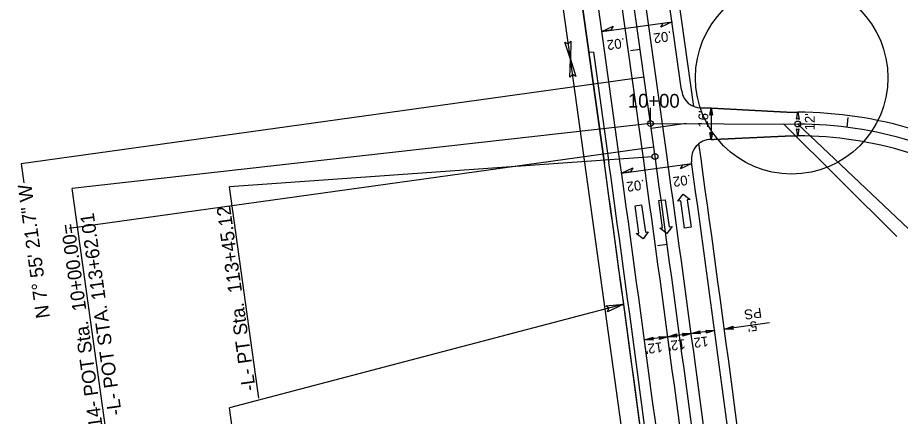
# Model space of a CAD drawing. Extents: x 472216 to 481979, y 489069 to 507339.
# Drawn here: x 477703.5 to 478152.3, y 497819.2 to 498021.9 of the extents above; entities that cross this region are included whole.
import ezdxf

# ---------------------------------------------------------------- set-up
doc = ezdxf.new("R2010")
doc.units = 0
for name, color, linetype in [('Old_Level_12', 7, 'Continuous'), ('Prop Drainage Structure Drop Inlet Grate 2 Narrow Slots and Sag Grates 840 24 CELL', 7, 'Continuous'), ('Prop Drainage Structure Drop Inlet Grate 2 Wide Slots and Sag Grates 840 22 Label', 7, 'Continuous'), ('Prop Drainage Structure Outlet Berm Ditch 850 10 CELL', 7, 'Continuous'), ('Prop Drainage Structure Pipe CSP 15in', 7, 'Continuous'), ('Prop Drainage Structure Pipe RCP 15in Class III Label', 7, 'Continuous'), ('Prop Drainage Structure Pipe RCP 24in Class III Label', 7, 'Continuous'), ('Prop Drainage Structure Pipe Side Drain 15in Label', 7, 'Continuous'), ('Prop Drainage Structure Tops and Inverts LABEL', 7, 'Continuous'), ('Prop Earthen Structure False Sump CELL', 7, 'Continuous'), ('Prop Erosion Embankment Toe Protection CELL', 7, 'Continuous'), ('Sheet Block Revision CELL', 7, 'Continuous'), ('Sheet Block Title CELL', 7, 'Continuous'), ('Sheet Clip Boundary CELL', 7, 'Continuous'), ('Sheet North Arrow Point CELL', 7, 'Continuous'), ('Sheet PE Seal Cell', 7, 'Continuous'), ('Sheet Plan And Profile CELL', 7, 'Continuous'), ('Sheet Plot Border Outside CELL', 7, 'Continuous'), ('Sheet Profile Grid Major CELL', 7, 'Continuous'), ('Sheet Profile Grid Minor CELL', 7, 'Continuous')]:
    doc.layers.add(name, color=color, linetype=linetype)

msp = doc.modelspace()

# ---------------------------------------------------------------- linework, layer by layer
at = {"layer": 'Old_Level_12'}
for p, q in [((478021.95, 497991.61), (477705.24, 497947.53)), ((478025.23, 497968.03), (477731.27, 497934.92)), ((478150.49, 497910.65), (478092.82, 497967.81)), ((478100.1, 497967.78), (478162.88, 497908.21)), ((478026.07, 497951.1), (477811.27, 497935.77)), ((477705.24, 497947.53), (477706.59, 497937.85)), ((477751.11, 497792.38), (477731.27, 497934.92)), ((477826.2, 497828.47), (477811.27, 497935.77))]:
    msp.add_line(p, q, dxfattribs=at)
for centre in [(478025.23, 497968.03), (478025.23, 497968.03), (478100.1, 497967.78), (478027.55, 497951.3), (478027.55, 497951.3)]:
    msp.add_circle(centre, 1.5, dxfattribs=at)
at = {"layer": 'Prop Drainage Structure Drop Inlet Grate 2 Narrow Slots and Sag Grates 840 24 CELL'}
for points in [[(478000.54, 498014.81), (478006.21, 498017.61), (478005.12, 498015.44)], [(478036.2, 498019.77), (478030.53, 498016.96), (478031.62, 498019.13)], [(478010.57, 497942.78), (478016.23, 497945.58), (478015.15, 497943.41)], [(478046.22, 497947.74), (478040.56, 497944.93), (478041.64, 497947.1)]]:
    msp.add_lwpolyline(points, close=True, dxfattribs=at)
at = {"layer": 'Prop Drainage Structure Drop Inlet Grate 2 Wide Slots and Sag Grates 840 22 Label'}
for p, q in [((478000.54, 498014.81), (478036.2, 498019.77)), ((478010.57, 497942.78), (478046.22, 497947.74))]:
    msp.add_line(p, q, dxfattribs=at)
at = {"layer": 'Prop Drainage Structure Outlet Berm Ditch 850 10 CELL'}
for points in [[(477984.81, 498009.85), (477984.51, 498000.72), (477981.68, 498009.46), (477983.42, 498008.55)], [(477984.22, 497991.59), (477984.51, 498000.72), (477987.34, 497991.98), (477985.6, 497992.9)], [(478055.47, 497972.33), (478056.1, 497975.93), (478056.73, 497972.31), (478056.09, 497972.77)], [(478099.49, 497970.19), (478100.12, 497973.78), (478100.75, 497970.16), (478100.11, 497970.62)], [(478056.68, 497963.53), (478056.05, 497959.93), (478055.42, 497963.55), (478056.06, 497963.09)], [(478100.71, 497965.38), (478100.08, 497961.78), (478099.45, 497965.41), (478100.09, 497964.94)], [(478002.54, 497875.38), (478011.64, 497876.17), (478003.3, 497872.32), (478004, 497874.16)], [(478067.42, 497863.38), (478062.86, 497863.54), (478067.23, 497864.94), (478066.77, 497864.07)], [(478038.68, 497859.48), (478034.12, 497859.65), (478038.5, 497861.05), (478038.04, 497860.18)], [(478041.45, 497861.42), (478046.01, 497861.26), (478041.64, 497859.86), (478042.1, 497860.73)], [(478050.58, 497861.09), (478046.01, 497861.26), (478050.39, 497862.66), (478049.93, 497861.79)], [(478053.34, 497863.03), (478057.9, 497862.87), (478053.53, 497861.47), (478053.99, 497862.34)], [(478026.79, 497857.87), (478022.23, 497858.04), (478026.61, 497859.44), (478026.14, 497858.57)], [(478029.56, 497859.81), (478034.12, 497859.65), (478029.74, 497858.25), (478030.21, 497859.12)]]:
    msp.add_lwpolyline(points, close=True, dxfattribs=at)
at = {"layer": 'Prop Drainage Structure Pipe RCP 15in Class III Label'}
for p, q in [((478033.5, 497952.13), (477983.76, 498309.54)), ((478021.61, 497950.48), (477971.78, 498308.52))]:
    msp.add_line(p, q, dxfattribs=at)
for radius in [21994, 22006]:
    msp.add_arc((456237.54, 494918.9), radius, 7.274664, 7.922681, dxfattribs=at)
at = {"layer": 'Prop Drainage Structure Pipe RCP 24in Class III Label'}
for p, q in [((478040.87, 497986.18), (477995.56, 498311.83)), ((478009.73, 497948.82), (477959.88, 498307.01)), ((477996.27, 498004.38), (477993.96, 498004.06)), ((478041.1, 497984.57), (478040.87, 497986.18)), ((478050.97, 497975.95), (478056.1, 497975.93)), ((478096.1, 497973.8), (478100.12, 497973.78)), ((478096.06, 497961.8), (478100.08, 497961.78))]:
    msp.add_line(p, q, dxfattribs=at)
for centre, radius, start, end in [((478051, 497985.95), 10, 187.9227, 269.8104), ((478099.44, 497767.78), 206, 56.2453, 89.8104), ((478056.01, 497949.93), 10, 89.8104, 187.9089), ((478099.44, 497767.78), 194, 56.2453, 89.8104), ((456237.54, 494918.9), 21982, 7.274664, 7.922681), ((456237.54, 494918.9), 22018, 7.274664, 7.90894)]:
    msp.add_arc(centre, radius, start, end, dxfattribs=at)
for points in [[(478056.1, 497975.93), (478056.64, 497975.9), (478057.18, 497975.87), (478057.72, 497975.84), (478058.26, 497975.81), (478058.8, 497975.78), (478059.35, 497975.76), (478059.89, 497975.73), (478060.43, 497975.7), (478060.97, 497975.67), (478061.51, 497975.64), (478062.05, 497975.61), (478062.59, 497975.58), (478063.13, 497975.55), (478063.67, 497975.53), (478064.21, 497975.5), (478064.75, 497975.47), (478065.29, 497975.44), (478065.83, 497975.41), (478066.37, 497975.38), (478066.91, 497975.35), (478067.45, 497975.32), (478067.99, 497975.29), (478068.53, 497975.27), (478069.07, 497975.24), (478069.61, 497975.21), (478070.15, 497975.18), (478070.69, 497975.15), (478071.23, 497975.12), (478071.78, 497975.09), (478072.32, 497975.06), (478072.86, 497975.04), (478073.4, 497975.01), (478073.94, 497974.98), (478074.48, 497974.95), (478075.02, 497974.92), (478075.56, 497974.89), (478076.1, 497974.86), (478076.64, 497974.83), (478077.18, 497974.8), (478077.72, 497974.78), (478078.26, 497974.75), (478078.8, 497974.72), (478079.34, 497974.69), (478079.88, 497974.66), (478080.42, 497974.63), (478080.96, 497974.6), (478081.5, 497974.57), (478082.04, 497974.55), (478082.58, 497974.52), (478083.12, 497974.49), (478083.67, 497974.46), (478084.21, 497974.43), (478084.75, 497974.4), (478085.29, 497974.37), (478085.83, 497974.34), (478086.37, 497974.32), (478086.91, 497974.29), (478087.45, 497974.26), (478087.99, 497974.23), (478088.53, 497974.2), (478089.07, 497974.17), (478089.61, 497974.14), (478090.15, 497974.11), (478090.69, 497974.08), (478091.23, 497974.06), (478091.77, 497974.03), (478092.31, 497974), (478092.85, 497973.97), (478093.39, 497973.94), (478093.93, 497973.91), (478094.47, 497973.88), (478095.01, 497973.85), (478096.1, 497973.8)], [(478056.05, 497959.93), (478056.59, 497959.95), (478057.13, 497959.98), (478057.67, 497960), (478058.21, 497960.03), (478058.75, 497960.06), (478059.29, 497960.08), (478059.83, 497960.11), (478060.37, 497960.13), (478060.92, 497960.16), (478061.46, 497960.18), (478062, 497960.21), (478062.54, 497960.23), (478063.08, 497960.26), (478063.62, 497960.28), (478064.16, 497960.31), (478064.7, 497960.33), (478065.24, 497960.36), (478065.78, 497960.38), (478066.32, 497960.41), (478066.86, 497960.43), (478067.4, 497960.46), (478067.94, 497960.48), (478068.48, 497960.51), (478069.02, 497960.53), (478069.57, 497960.56), (478070.11, 497960.59), (478070.65, 497960.61), (478071.19, 497960.64), (478071.73, 497960.66), (478072.27, 497960.69), (478072.81, 497960.71), (478073.35, 497960.74), (478073.89, 497960.76), (478074.43, 497960.79), (478074.97, 497960.81), (478075.51, 497960.84), (478076.05, 497960.86), (478076.59, 497960.89), (478077.13, 497960.91), (478077.67, 497960.94), (478078.22, 497960.96), (478078.76, 497960.99), (478079.3, 497961.01), (478079.84, 497961.04), (478080.38, 497961.06), (478080.92, 497961.09), (478081.46, 497961.12), (478082, 497961.14), (478082.54, 497961.17), (478083.08, 497961.19), (478083.62, 497961.22), (478084.16, 497961.24), (478084.7, 497961.27), (478085.24, 497961.29), (478085.78, 497961.32), (478086.32, 497961.34), (478086.87, 497961.37), (478087.41, 497961.39), (478087.95, 497961.42), (478088.49, 497961.44), (478089.03, 497961.47), (478089.57, 497961.49), (478090.11, 497961.52), (478090.65, 497961.54), (478091.19, 497961.57), (478091.73, 497961.59), (478092.27, 497961.62), (478092.81, 497961.65), (478093.35, 497961.67), (478093.89, 497961.7), (478094.43, 497961.72), (478094.97, 497961.75), (478096.06, 497961.8)]]:
    msp.add_spline(points, degree=3, dxfattribs=at)
at = {"layer": 'Prop Drainage Structure Pipe Side Drain 15in Label'}
for p, q in [((478039.19, 497928.51), (478041.82, 497932.06)), ((478041.82, 497932.06), (478045.43, 497929.38)), ((478029.49, 497928.85), (478032.76, 497929.3)), ((478031.42, 497914.98), (478029.49, 497928.85)), ((478032.76, 497929.3), (478034.69, 497915.44)), ((478040.67, 497928.72), (478039.19, 497928.51)), ((478042.6, 497914.85), (478040.67, 497928.72)), ((478045.43, 497929.38), (478043.94, 497929.17)), ((478043.94, 497929.17), (478045.87, 497915.3)), ((478017.44, 497926.23), (478020.71, 497926.68)), ((478019.37, 497912.36), (478017.44, 497926.23)), ((478020.71, 497926.68), (478022.64, 497912.81)), ((478029.94, 497914.77), (478031.42, 497914.98)), ((478033.54, 497912.09), (478029.94, 497914.77)), ((478036.18, 497915.64), (478033.54, 497912.09)), ((478034.69, 497915.44), (478036.18, 497915.64)), ((478045.87, 497915.3), (478042.6, 497914.85)), ((478017.88, 497912.15), (478019.37, 497912.36)), ((478021.49, 497909.47), (478017.88, 497912.15)), ((478024.12, 497913.02), (478021.49, 497909.47)), ((478022.64, 497912.81), (478024.12, 497913.02))]:
    msp.add_line(p, q, dxfattribs=at)
at = {"layer": 'Prop Drainage Structure Tops and Inverts LABEL'}
msp.add_line((477951.94, 498306.01), (478001.8, 497947.72), dxfattribs=at)
msp.add_arc((456237.54, 494918.9), 21974, 7.274664, 7.922681, dxfattribs=at)
at = {"layer": 'Prop Earthen Structure False Sump CELL'}
msp.add_line((477996.27, 498004.38), (478004.11, 497948.04), dxfattribs=at)
msp.add_arc((456237.54, 494918.9), 21976.33, 7.275189, 7.922681, dxfattribs=at)
at = {"layer": 'Prop Erosion Embankment Toe Protection CELL'}
for p, q in [((478047.24, 497976.68), (478000.5, 498312.58)), ((478001.8, 497947.72), (477951.94, 498306.01)), ((477977.01, 498125.88), (478001.8, 497947.72))]:
    msp.add_line(p, q, dxfattribs=at)
for radius, end in [(22023, 7.931468), (21974, 7.919388)]:
    msp.add_arc((456237.54, 494918.9), radius, 7.274664, end, dxfattribs=at)
at = {"layer": 'Sheet Block Revision CELL'}
for p, q in [((477984.51, 498000.72), (477969.82, 498106.32)), ((478046.5, 497555.31), (477984.51, 498000.72)), ((478056.1, 497975.93), (478056.05, 497959.93)), ((478011.64, 497876.17), (477811.29, 497823.42)), ((478085.67, 497866.63), (478062.86, 497863.54)), ((478057.9, 497862.87), (478022.23, 497858.04)), ((477820.73, 497755.61), (477811.29, 497823.42))]:
    msp.add_line(p, q, dxfattribs=at)
at = {"layer": 'Sheet Block Title CELL'}
msp.add_line((477729.74, 497914.79), (478026.88, 497956.14), dxfattribs=at)
at = {"layer": 'Sheet Clip Boundary CELL'}
msp.add_line((478043.41, 497967.97), (478025.58, 497965.49), dxfattribs=at)
at = {"layer": 'Sheet North Arrow Point CELL'}
for p, q in [((478027.55, 497951.3), (477897.19, 498888.08)), ((478025.23, 497968.03), (478100.1, 497967.78))]:
    msp.add_line(p, q, dxfattribs=at)
for centre, radius, start, end in [((478099.44, 497767.78), 200, 56.2453, 89.8104), ((456237.54, 494918.9), 22000, 7.274664, 7.922681)]:
    msp.add_arc(centre, radius, start, end, dxfattribs=at)
at = {"layer": 'Sheet PE Seal Cell'}
for p, q in [((478019.99, 498005.66), (478015.04, 498004.97)), ((478125.15, 497966.12), (478125.8, 497971.08)), ((478033.73, 497906.61), (478028.77, 497905.93))]:
    msp.add_line(p, q, dxfattribs=at)
at = {"layer": 'Sheet Plot Border Outside CELL'}
msp.add_circle((478097, 497991.31), 48.94, dxfattribs=at)
at = {"layer": 'Sheet Profile Grid Minor CELL'}
msp.add_line((478025.23, 497968.03), (478025.25, 497976.03), dxfattribs=at)

# ---------------------------------------------------------------- texts
at = {"layer": 'Old_Level_12'}
for s, p in [('-L- PT Sta.  113+45.12', (477824.59, 497832.53)), ('-L- POT STA. 113+62.01', (477756.48, 497820.09)), ('-DR14- POT Sta.  10+00.00=', (477749.02, 497797.52))]:
    msp.add_text(s, height=7, rotation=97.9227, dxfattribs=at).set_placement(p)
at = {"layer": 'Prop Drainage Structure Drop Inlet Grate 2 Narrow Slots and Sag Grates 840 24 CELL'}
for p in [(478035.74, 498015.03), (478012, 498011.54), (478045.56, 497942.04), (478022.02, 497939.51)]:
    msp.add_text('.02', height=5, rotation=187.9227, dxfattribs=at).set_placement(p)
at = {"layer": 'Prop Drainage Structure Pipe CSP 15in'}
for s, rotation, p in [("16'", 87.78, (478054.41, 497965.82)), ("12'", 89.8071, (478108.72, 497964.51)), ('PS', 187.7177, (478081.44, 497874.43)), ("5'", 187.7177, (478079.17, 497867.72)), ("12'", 187.7177, (478031.03, 497856.92)), ("12'", 187.7177, (478042.66, 497858.5)), ("12'", 187.7177, (478054.3, 497859.9))]:
    msp.add_text(s, height=5, rotation=rotation, dxfattribs=at).set_placement(p)
at = {"layer": 'Sheet Plan And Profile CELL'}
msp.add_text('N 7%%d 55\' 21.7" W', height=7, rotation=97.9227, dxfattribs=at).set_placement((477719.92, 497869.49))
at = {"layer": 'Sheet Profile Grid Major CELL'}
msp.add_text('10+00', height=7, rotation=359.8104, dxfattribs=at).set_placement((478013.75, 497976.15))

doc.saveas('drawing.dxf')
